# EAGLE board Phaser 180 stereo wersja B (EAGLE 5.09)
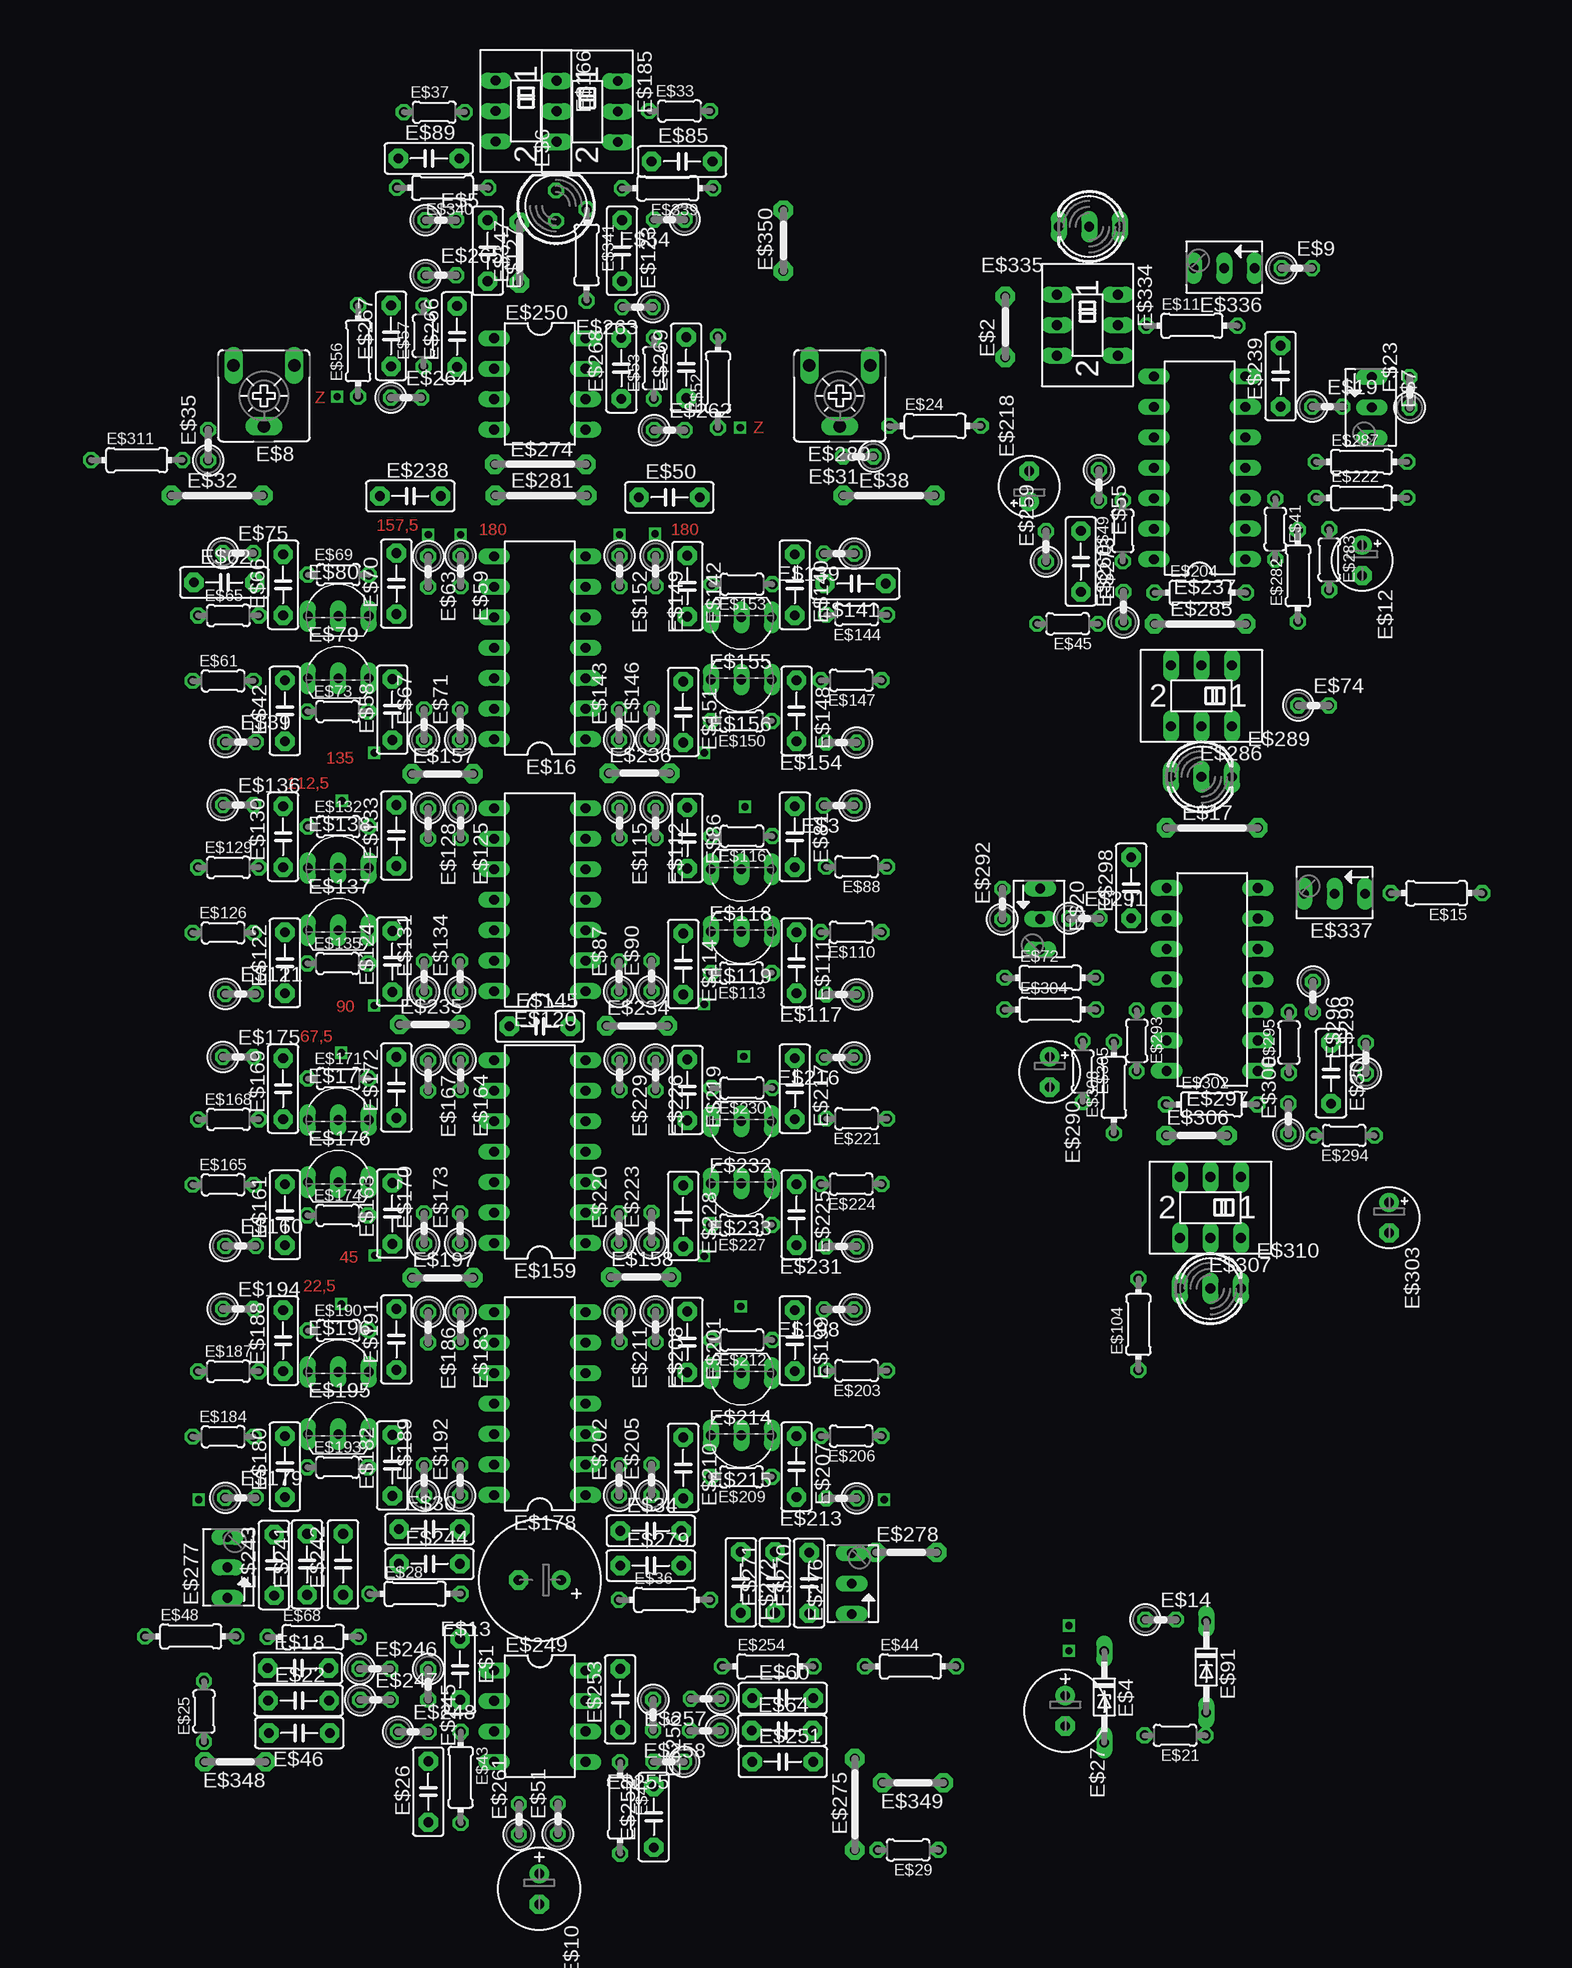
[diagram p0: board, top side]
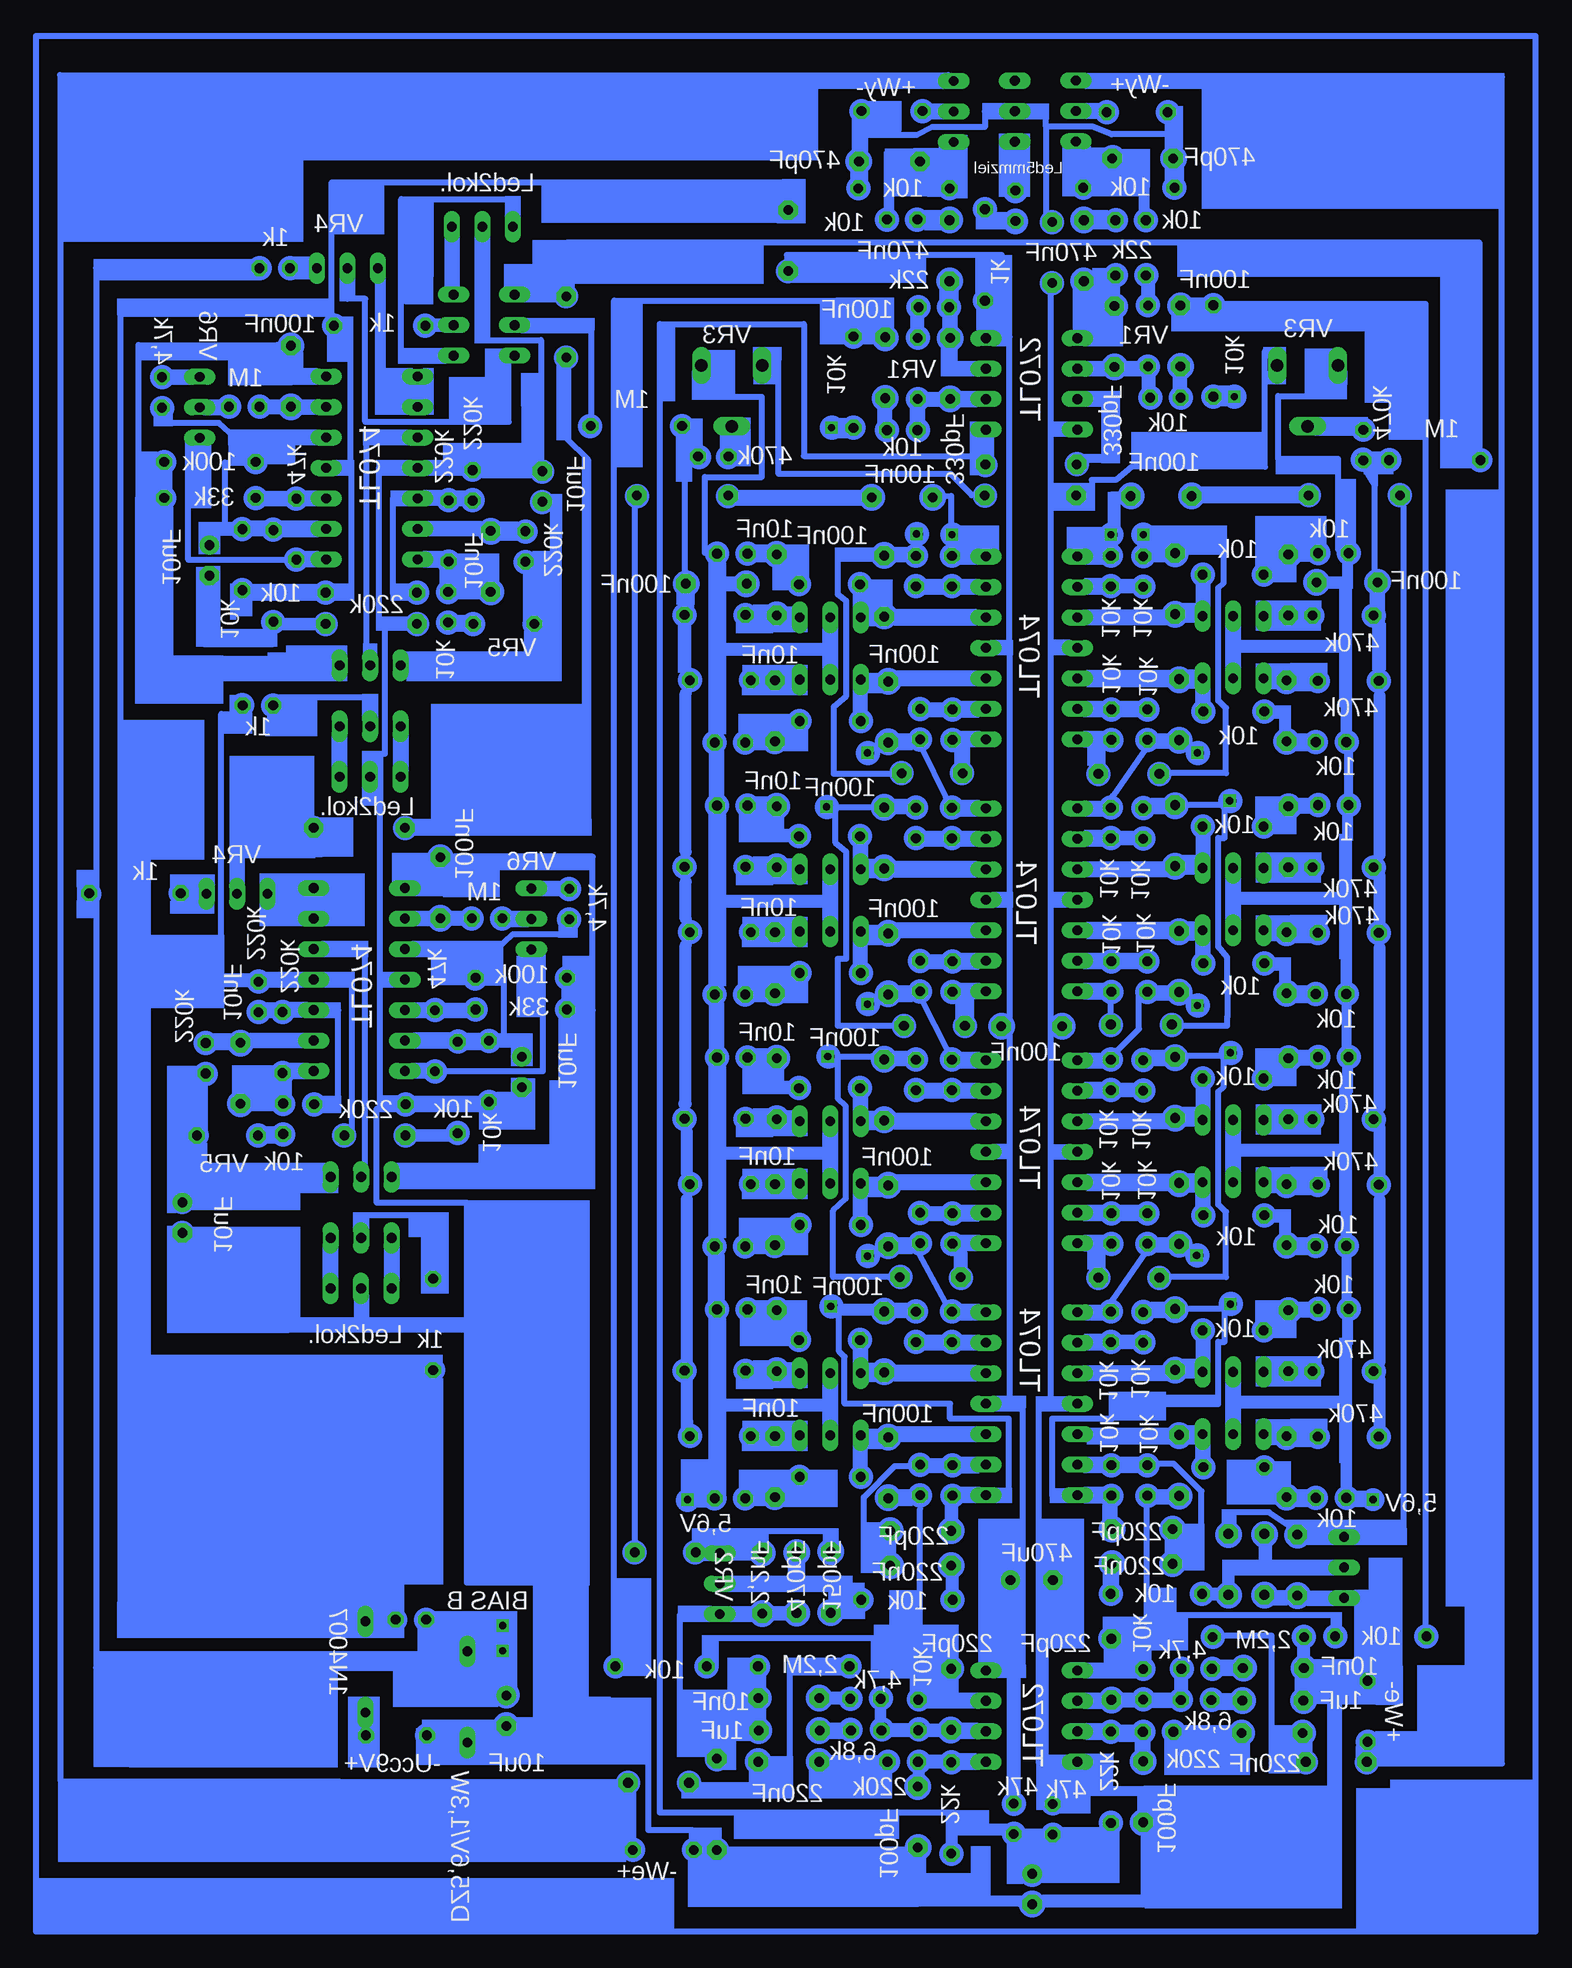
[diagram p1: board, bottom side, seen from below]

No outline drawn. Coordinates in mm, seen from the top.
Copper layers (1*16): Top 0.035mm / dielectric 1.5mm / Bottom 0.035mm
Design rules "default": minimum track width 10mil, minimum drill 24mil, track to track 8mil, track to pad 8mil, pad to pad 8mil, via to via 8mil, smd to smd 8mil, copper to edge 40mil, drill to drill 8mil, minimum pad ring 10mil, minimum via ring 8mil, stop-mask expansion 4mil, vias tented up to drill 0mil, thermal gap 10mil

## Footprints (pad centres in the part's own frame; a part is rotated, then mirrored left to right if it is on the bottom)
C5B2.5 = drill 0.813 pad 1.6 octagon: 1 -2.54,0; 2 2.54,0
05 = drill 0.813 pad 1.6 octagon: 1 -2.54,0; 2 2.54,0
0207/2V = drill 0.813 octagon: 1 -1.27,0; 2 1.27,0
DO34Z7 = drill 0.813 long: A 3.81,0; C -3.81,0
LED5MM = drill 0.813 octagon: A -1.27,0; K 1.27,0
B64Y = drill 0.813 long: A 2.54,0; E -2.54,0; S 0,0
CA6V = drill 1.016 long: A -2.54,-2.54; E 2.54,-2.54; S 0,2.54
E2,5-7 = drill 0.813 pad 1.6 round: + -1.27,0 | drill 0.813 pad 1.6 octagon: - 1.27,0
0204/7 = drill 0.813 octagon: 1 -3.81,0; 2 3.81,0
E2,5-5 = drill 0.813 pad 1.6 round: + -1.27,0 | drill 0.813 pad 1.6 octagon: - 1.27,0
E3,5-10 = drill 0.813 pad 1.6 round: + -1.778,0 | drill 0.813 pad 1.6 octagon: - 1.778,0
DIL14 = drill 0.813 long: 1 -7.62,-3.81; 2 -5.08,-3.81; 3 -2.54,-3.81; 4 0,-3.81; 5 2.54,-3.81; 6 5.08,-3.81; 7 7.62,-3.81; 8 7.62,3.81; 9 5.08,3.81; 10 2.54,3.81; 11 0,3.81; 12 -2.54,3.81; 13 -5.08,3.81; 14 -7.62,3.81
07 = drill 0.813 pad 1.6 octagon: 1 -3.81,0; 2 3.81,0
0204/5 = drill 0.813 octagon: 1 -2.54,0; 2 2.54,0
TO92- = drill 0.813 long: 1 2.54,0; 2 0,0; 3 -2.54,0
DO34-7 = drill 0.813 long: A 3.81,0; C -3.81,0
A68-A31 = drill 0.813 long: 1 -2.54,-2.54; 2 0,-2.54; 3 2.54,-2.54; 4 -2.54,2.54; 5 0,2.54; 6 2.54,2.54
DIL08 = drill 0.813 long: 1 -3.81,-3.81; 2 -1.27,-3.81; 3 1.27,-3.81; 4 3.81,-3.81; 5 3.81,3.81; 6 1.27,3.81; 7 -1.27,3.81; 8 -3.81,3.81
DUOLED-A-5MM = drill 0.813 long: A 0,0; CR 2.54,0; CX -2.54,0

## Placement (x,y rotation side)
E$1  [C5B2.5]  35.65,22.15 270 top
E$2  [05]  81.1,134.05 90 top
E$3  [0207/2V]  67.25,94.15 180 top
E$4  [DO34Z7]  89.35,19.85 270 top
E$5  [0207/2V]  34.05,142.95 0 top
E$6  [LED5MM]  43.65,144.15 90 top
E$7  [B64Y]  111.65,127.35 270 top
E$8  [CA6V]  19.3,128.3 180 top
E$9  [0207/2V]  105.4,138.95 0 top
E$10  [E2,5-7]  42.25,3.85 270 top
E$11  [0204/7]  96.65,134.15 0 top
E$12  [E2,5-5]  110.85,114.6 270 top
E$13  [E3,5-10]  42.3,29.6 180 top
E$14  [0207/2V]  94.05,26.3 0 top
E$15  [0204/7]  117.05,86.85 180 top
E$16  [DIL14]  42.3,107.3 90 top
E$17  [07]  98.35,92.3 0 top
E$18  [C5B2.5]  22.15,22.25 0 top
E$19  [0207/2V]  107.95,127.4 0 top
E$20  [B64Y]  84,84.7 270 top
E$21  [0204/5]  95.25,16.65 180 top
E$22  [C5B2.5]  22.2,19.55 0 top
E$23  [0207/2V]  114.8,128.6 90 top
E$24  [0204/7]  75.25,125.8 0 top
E$25  [0204/5]  14.3,18.65 90 top
E$26  [C5B2.5]  33,11.95 90 top
E$27  [E2,5-7]  86.1,18.7 270 top
E$28  [0204/7]  31.9,28.45 0 top
E$29  [0204/5]  73,7.1 180 top
E$30  [C5B2.5]  33.1,33.85 0 top
E$31  [0207/2V]  68.85,123.25 180 top
E$32  [07]  15.4,120 0 top
E$33  [0204/5]  53.95,152.05 0 top
E$34  [C5B2.5]  51.55,33.7 0 top
E$35  [0207/2V]  14.65,124.2 90 top
E$36  [0204/7]  52.7,27.95 0 top
E$37  [0204/5]  33.5,151.95 0 top
E$38  [07]  71.4,120 0 top
E$39  [0207/2V]  17.35,99.45 0 top
E$41  [0204/5]  103.6,117.2 270 top
E$42  [C5B2.5]  21.05,102.05 90 top
E$43  [0204/7]  35.7,13.15 270 top
E$44  [0204/7]  73.2,22.4 0 top
E$45  [0204/5]  86.3,109.3 180 top
E$46  [C5B2.5]  22.25,16.85 180 top
E$47  [0204/7]  49,10.6 270 top
E$48  [0204/7]  13.2,24.9 0 top
E$49  [0204/5]  90.9,117.05 90 top
E$50  [C5B2.5]  53.1,119.85 0 top
E$51  [0207/2V]  43.8,9.7 90 top
E$52  [0204/7]  57.15,129.45 90 top
E$53  [0204/5]  51.8,130.6 90 top
E$54  [0207/2V]  53.1,143 180 top
E$55  [0207/2V]  88.9,120.85 270 top
E$56  [0204/7]  27.15,132.05 90 top
E$57  [0204/5]  32.6,133.3 90 top
E$58  [C5B2.5]  30,102.15 90 top
E$59  [0207/2V]  35.7,113.7 270 top
E$60  [C5B2.5]  62.55,19.75 0 top
E$61  [0204/5]  15.9,104.55 0 top
E$62  [C5B2.5]  16,112.75 0 top
E$63  [0207/2V]  33,113.65 270 top
E$64  [C5B2.5]  62.5,17.05 0 top
E$65  [0204/5]  16.35,110 0 top
E$66  [C5B2.5]  20.9,112.55 90 top
E$67  [0207/2V]  32.65,100.9 90 top
E$68  [0204/7]  23.4,24.85 0 top
E$69  [0204/5]  25.5,113.4 0 top
E$70  [C5B2.5]  30.35,112.65 90 top
E$71  [0207/2V]  35.65,100.9 90 top
E$72  [0204/7]  84.85,79.8 0 top
E$73  [0204/5]  25.45,102 0 top
E$74  [0207/2V]  106.8,102.5 0 top
E$75  [0207/2V]  17.15,115.2 0 top
E$79  [TO92-]  25.5,104.75 0 top
E$80  [TO92-]  25.5,109.95 0 top
E$81  [C5B2.5]  63.55,91.55 270 top
E$85  [C5B2.5]  54.15,147.85 0 top
E$86  [C5B2.5]  54.6,91.45 270 top
E$87  [0207/2V]  48.9,79.9 90 top
E$88  [0204/5]  68.7,89.05 180 top
E$89  [C5B2.5]  33.05,148.1 0 top
E$90  [0207/2V]  51.6,79.95 90 top
E$91  [DO34-7]  97.85,22.35 270 top
E$104  [0204/7]  92.2,50.9 90 top
E$110  [0204/5]  68.25,83.6 180 top
E$111  [C5B2.5]  63.7,81.05 270 top
E$112  [0207/2V]  51.95,92.7 270 top
E$113  [0204/5]  59.1,80.2 180 top
E$114  [C5B2.5]  54.25,80.95 270 top
E$115  [0207/2V]  48.95,92.7 270 top
E$116  [0204/5]  59.15,91.6 180 top
E$117  [0207/2V]  67.45,78.4 180 top
E$118  [TO92-]  59.1,88.85 180 top
E$119  [TO92-]  59.1,83.65 180 top
E$120  [DIL14]  42.3,86.3 90 top
E$121  [0207/2V]  17.35,78.45 0 top
E$122  [C5B2.5]  21.05,81.05 90 top
E$123  [C5B2.5]  49.15,140.4 270 top
E$124  [C5B2.5]  30,81.15 90 top
E$125  [0207/2V]  35.7,92.7 270 top
E$126  [0204/5]  15.9,83.55 0 top
E$127  [C5B2.5]  37.95,140.4 270 top
E$128  [0207/2V]  33,92.65 270 top
E$129  [0204/5]  16.35,89 0 top
E$130  [C5B2.5]  20.9,91.55 90 top
E$131  [0207/2V]  32.65,79.9 90 top
E$132  [0204/5]  25.5,92.4 0 top
E$133  [C5B2.5]  30.35,91.65 90 top
E$134  [0207/2V]  35.65,79.9 90 top
E$135  [0204/5]  25.45,81 0 top
E$136  [0207/2V]  17.15,94.2 0 top
E$137  [TO92-]  25.5,83.75 0 top
E$138  [TO92-]  25.5,88.95 0 top
E$139  [0207/2V]  67.25,115.15 180 top
E$140  [C5B2.5]  63.55,112.55 270 top
E$141  [C5B2.5]  68.6,112.65 180 top
E$142  [C5B2.5]  54.6,112.45 270 top
E$143  [0207/2V]  48.9,100.9 90 top
E$144  [0204/5]  68.7,110.05 180 top
E$145  [C5B2.5]  42.3,75.75 0 top
E$146  [0207/2V]  51.6,100.95 90 top
E$147  [0204/5]  68.25,104.6 180 top
E$148  [C5B2.5]  63.7,102.05 270 top
E$149  [0207/2V]  51.95,113.7 270 top
E$150  [0204/5]  59.1,101.2 180 top
E$151  [C5B2.5]  54.25,101.95 270 top
E$152  [0207/2V]  48.95,113.7 270 top
E$153  [0204/5]  59.15,112.6 180 top
E$154  [0207/2V]  67.45,99.4 180 top
E$155  [TO92-]  59.1,109.85 180 top
E$156  [TO92-]  59.1,104.65 180 top
E$157  [05]  34.2,96.8 0 top
E$158  [05]  50.75,54.85 0 top
E$159  [DIL14]  42.3,65.3 90 top
E$160  [0207/2V]  17.35,57.45 0 top
E$161  [C5B2.5]  21.05,60.05 90 top
E$163  [C5B2.5]  30,60.15 90 top
E$164  [0207/2V]  35.7,71.7 270 top
E$165  [0204/5]  15.9,62.55 0 top
E$166  [A68-A31]  41.15,152.05 270 top
E$167  [0207/2V]  33,71.65 270 top
E$168  [0204/5]  16.35,68 0 top
E$169  [C5B2.5]  20.9,70.55 90 top
E$170  [0207/2V]  32.65,58.9 90 top
E$171  [0204/5]  25.5,71.4 0 top
E$172  [C5B2.5]  30.35,70.65 90 top
E$173  [0207/2V]  35.65,58.9 90 top
E$174  [0204/5]  25.45,60 0 top
E$175  [0207/2V]  17.15,73.2 0 top
E$176  [TO92-]  25.5,62.75 0 top
E$177  [TO92-]  25.5,67.95 0 top
E$178  [DIL14]  42.3,44.3 90 top
E$179  [0207/2V]  17.35,36.45 0 top
E$180  [C5B2.5]  21.05,39.05 90 top
E$182  [C5B2.5]  30,39.15 90 top
E$183  [0207/2V]  35.7,50.7 270 top
E$184  [0204/5]  15.9,41.55 0 top
E$185  [A68-A31]  46.25,152 270 top
E$186  [0207/2V]  33,50.65 270 top
E$187  [0204/5]  16.35,47 0 top
E$188  [C5B2.5]  20.9,49.55 90 top
E$189  [0207/2V]  32.65,37.9 90 top
E$190  [0204/5]  25.5,50.4 0 top
E$191  [C5B2.5]  30.35,49.65 90 top
E$192  [0207/2V]  35.65,37.9 90 top
E$193  [0204/5]  25.45,39 0 top
E$194  [0207/2V]  17.15,52.2 0 top
E$195  [TO92-]  25.5,41.75 0 top
E$196  [TO92-]  25.5,46.95 0 top
E$197  [05]  34.2,54.8 0 top
E$198  [0207/2V]  67.25,52.15 180 top
E$199  [C5B2.5]  63.55,49.55 270 top
E$201  [C5B2.5]  54.6,49.45 270 top
E$202  [0207/2V]  48.9,37.9 90 top
E$203  [0204/5]  68.7,47.05 180 top
E$204  [0204/7]  97.35,111.9 0 top
E$205  [0207/2V]  51.6,37.95 90 top
E$206  [0204/5]  68.25,41.6 180 top
E$207  [C5B2.5]  63.7,39.05 270 top
E$208  [0207/2V]  51.95,50.7 270 top
E$209  [0204/5]  59.1,38.2 180 top
E$210  [C5B2.5]  54.25,38.95 270 top
E$211  [0207/2V]  48.95,50.7 270 top
E$212  [0204/5]  59.15,49.6 180 top
E$213  [0207/2V]  67.45,36.4 180 top
E$214  [TO92-]  59.1,46.85 180 top
E$215  [TO92-]  59.1,41.65 180 top
E$216  [0207/2V]  67.25,73.15 180 top
E$217  [C5B2.5]  63.55,70.55 270 top
E$218  [E2,5-5]  83.1,120.75 90 top
E$219  [C5B2.5]  54.6,70.45 270 top
E$220  [0207/2V]  48.9,58.9 90 top
E$221  [0204/5]  68.7,68.05 180 top
E$222  [0204/7]  110.8,119.8 0 top
E$223  [0207/2V]  51.6,58.95 90 top
E$224  [0204/5]  68.25,62.6 180 top
E$225  [C5B2.5]  63.7,60.05 270 top
E$226  [0207/2V]  51.95,71.7 270 top
E$227  [0204/5]  59.1,59.2 180 top
E$228  [C5B2.5]  54.25,59.95 270 top
E$229  [0207/2V]  48.95,71.7 270 top
E$230  [0204/5]  59.15,70.6 180 top
E$231  [0207/2V]  67.45,57.4 180 top
E$232  [TO92-]  59.1,67.85 180 top
E$233  [TO92-]  59.1,62.65 180 top
E$234  [05]  50.4,75.8 0 top
E$235  [05]  33.15,75.9 0 top
E$236  [05]  50.6,96.85 0 top
E$237  [DIL14]  97.3,122.3 90 top
E$238  [C5B2.5]  31.5,119.95 0 top
E$239  [C5B2.5]  104.05,129.95 90 top
E$241  [C5B2.5]  22.9,30.9 90 top
E$242  [C5B2.5]  25.9,30.9 90 top
E$243  [C5B2.5]  20.15,30.85 90 top
E$244  [C5B2.5]  33.1,30.95 0 top
E$245  [0207/2V]  33,20.9 270 top
E$246  [0207/2V]  28.55,22.2 0 top
E$247  [0207/2V]  28.6,19.6 0 top
E$248  [0207/2V]  31.75,16.95 0 top
E$249  [DIL08]  42.3,18.25 270 top
E$250  [DIL08]  42.3,129.3 270 top
E$251  [C5B2.5]  62.55,14.45 0 top
E$252  [C5B2.5]  51.8,9.85 90 top
E$253  [C5B2.5]  49,19.65 90 top
E$254  [0204/7]  61.3,22.4 0 top
E$255  [0207/2V]  53.05,14.45 180 top
E$256  [0207/2V]  51.75,18.35 270 top
E$257  [0207/2V]  56.15,19.7 180 top
E$258  [0207/2V]  56.1,17.05 180 top
E$259  [0207/2V]  84.5,115.75 90 top
E$260  [0207/2V]  90.95,110.7 90 top
E$261  [0207/2V]  40.55,9.65 90 top
E$262  [0207/2V]  53.1,125.45 0 top
E$263  [0207/2V]  50.45,135.7 180 top
E$264  [0207/2V]  31.15,128.15 0 top
E$265  [0207/2V]  34.05,138.35 0 top
E$266  [C5B2.5]  35.4,133.25 90 top
E$267  [C5B2.5]  29.9,133.3 90 top
E$268  [C5B2.5]  49.1,130.6 90 top
E$269  [C5B2.5]  54.5,130.65 90 top
E$270  [C5B2.5]  64.75,29.35 90 top
E$271  [C5B2.5]  61.9,29.4 90 top
E$272  [C5B2.5]  59.05,29.4 270 top
E$273  [C5B2.5]  87.4,114.5 270 top
E$274  [07]  42.35,122.6 0 top
E$275  [07]  68.55,10.9 90 top
E$276  [B64Y]  68.3,29.3 90 top
E$277  [B64Y]  16.25,30.65 90 top
E$278  [05]  72.85,31.9 0 top
E$279  [C5B2.5]  51.55,30.8 0 top
E$280  [CA6V]  67.3,128.3 180 top
E$281  [07]  42.4,120 0 top
E$282  [0204/7]  105.5,113.3 90 top
E$283  [0204/5]  108.1,114.65 270 top
E$285  [07]  97.35,109.3 0 top
E$286  [A68-A31]  97.45,103.3 180 top
E$287  [0204/7]  110.8,122.8 0 top
E$289  [DUOLED-A-5MM]  97.45,96.55 0 top
E$290  [E2,5-5]  84.8,71.95 270 top
E$291  [0207/2V]  87.7,84.75 0 top
E$292  [0207/2V]  80.85,85.95 90 top
E$293  [0204/5]  92.05,74.55 270 top
E$294  [0204/5]  109.35,66.65 180 top
E$295  [0204/5]  104.75,74.4 90 top
E$296  [0207/2V]  106.75,78.2 270 top
E$297  [DIL14]  98.35,79.65 90 top
E$298  [C5B2.5]  91.6,87.3 90 top
E$299  [0207/2V]  111.15,73.1 90 top
E$300  [0207/2V]  104.7,68.05 90 top
E$301  [C5B2.5]  108.25,71.85 270 top
E$302  [0204/7]  98.3,69.25 0 top
E$303  [E2,5-5]  113.1,59.8 270 top
E$304  [0204/7]  84.85,77.15 0 top
E$305  [0204/5]  87.55,72 270 top
E$306  [05]  97.05,66.65 0 top
E$307  [A68-A31]  98.2,60.65 180 top
E$308  [0204/7]  90.15,70.65 90 top
E$310  [DUOLED-A-5MM]  98.2,53.9 0 top
E$311  [0204/7]  8.7,122.95 0 top
E$334  [A68-A31]  87.95,134.2 270 top
E$335  [DUOLED-A-5MM]  88.1,142.4 180 top
E$336  [B64Y]  99.35,138.95 180 top
E$337  [B64Y]  108.55,86.8 180 top
E$339  [0204/7]  52.95,145.6 180 top
E$340  [0204/7]  34.2,145.65 180 top
E$341  [0204/7]  46.2,140.05 270 top
E$347  [05]  40.6,140.25 90 top
E$348  [05]  16.9,14.45 180 top
E$349  [05]  73.4,12.7 180 top
E$350  [05]  62.6,141.25 90 top

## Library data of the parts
E$1 E$18 E$22 E$26 E$30 E$34 E$42 E$46 E$50 E$58 E$60 E$62 E$64 E$66 E$70 E$81 E$85 E$86 E$89 E$111 E$114 E$122-E$124 E$127 E$130 E$133 E$140-E$142 E$145 E$148 E$151 E$161 E$163 E$169 E$172 E$180 E$182 E$188 E$191 E$199 E$201 E$207 E$210 E$217 E$219 E$225 E$228 E$238 E$239 E$241-E$244 E$251-E$253 E$266-E$273 E$279 E$298 E$301 = capacitor-wima
E$2 E$17 E$32 E$38 E$157 E$158 E$197 E$234-E$236 E$274 E$275 E$278 E$281 E$285 E$306 E$347-E$350 = jumper
E$3 E$5 E$9-E$15 E$19 E$21 E$23-E$25 E$27-E$29 E$31 E$33 E$35-E$37 E$39 E$41 E$43-E$45 E$47-E$49 E$51-E$57 E$59 E$61 E$63 E$65 E$67-E$69 E$71-E$75 E$87 E$88 E$90 E$104 E$110 E$112 E$113 E$115-E$117 E$121 E$125 E$126 E$128 E$129 E$131 E$132 E$134-E$136 E$139 E$143 E$144 E$146 E$147 E$149 E$150 E$152-E$154 E$160 E$164 E$165 E$167 E$168 E$170 E$171 E$173-E$175 E$179 E$183 E$184 E$186 E$187 E$189 E$190 E$192-E$194 E$198 E$202-E$206 E$208 E$209 E$211-E$213 E$216 E$218 E$220-E$224 E$226 E$227 E$229-E$231 E$245-E$248 E$254-E$265 E$282 E$283 E$287 E$290-E$296 E$299 E$300 E$302-E$305 E$308 E$311 E$339-E$341 = rcl
E$4 E$91 = diode
E$6 E$289 E$310 E$335 = led
E$7 E$8 E$20 E$276 E$277 E$280 E$336 E$337 = pot
E$16 E$120 E$159 E$178 E$237 E$249 E$250 E$297 = analog-devices
E$79 E$80 E$118 E$119 E$137 E$138 E$155 E$156 E$176 E$177 E$195 E$196 E$214 E$215 E$232 E$233 = transistor-fet
E$166 E$185 E$286 E$307 E$334 = switch

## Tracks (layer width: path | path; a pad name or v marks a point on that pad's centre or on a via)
S$1
  Bottom 0.5: 81,137.65 81,141.1 5,141.1 5,123.85
S$2
  Bottom 0.5: 96.5,79.85 96.6,79.85 96.6,94.65 97.4,94.65 97.4,95.75
S$3
  Bottom 0.5: 37.05,145.65 32.8,145.65 32.8,143.8
S$4
  Bottom 0.5: 107.7,79.6 109.85,79.6 109.85,101.8 108.1,101.8 108.1,101.85
S$5
  Bottom 0.5: 108.55,87.65 108.55,92.3 103,92.3
S$6
  Bottom 0.5: 97.5,103.05 97.5,103.15 105.65,103.15
S$7
  Bottom 0.5: 51.45,145.9 54.35,145.9 54.35,143.9
S$8
  Bottom 0.5: 81.1,130.6 81.1,124.8 79.3,123 79.3,92.35 93.65,92.35
S$9
  Bottom 0.5: 98.2,53 98.2,50.6 89.5,50.6
S$12
  Bottom 0.5: 87.75,79.8 86.3,79.8 86.3,75.1
S$41
  Bottom 0.406: 17.65,112.8 15.8,112.8 15.8,114.5
S$42
  Bottom 0.406: 68.8,80.8 68.8,79.1
S$43
  Bottom 0.406: 15.8,93.5 15.8,91.8
S$44
  Bottom 0.406: 68.8,101.8 68.8,100.1
S$45
  Bottom 0.5: 32.8,98.9 35.55,94.95
S$46
  Bottom 0.5: 29.15,94.2 26.2,94.2 26.2,91.45 26.75,91.45 26.75,82.4 26,81.5 26,78.55
S$47
  Bottom 0.5: 26,78.6 26,76.5
S$48
  Bottom 0.5: 30.8,96.85 26.1,96.85 26.1,102.3 26.75,102.9 26.75,112.3 26.3,112.7 26.3,115.3 29.5,115.3
S$49
  Bottom 0.5: 45.1,36.65 44.2,36.65 44.2,43.05 49.1,43.05 49.1,44.3 57.9,44.3 57.9,48.2 58.35,48.65 58.35,52.2 55.75,52.2
S$50
  Bottom 0.5: 49.5,52.75 51.65,56.75
S$51
  Bottom 0.5: 54.2,54.85 58.85,54.85 58.85,60.4 57.8,61.4 57.8,69.1 58.45,69.75 58.45,73.25 55.65,73.25
S$52
  Bottom 0.5: 49.35,73.85 51.4,77.85
S$53
  Bottom 0.406: 15.8,70.8 15.8,72.5
S$54
  Bottom 0.406: 15.8,49.8 15.8,51.5
S$55
  Bottom 0.5: 35.55,52.95 32.8,56.9
S$56
  Bottom 0.5: 29.15,52.2 26.2,52.2 26.2,49.45 26.75,49.45
S$57
  Bottom 0.5: 39.55,36.65 40.6,36.65 40.6,43.05 35.6,43.05 35.6,44.25 26.75,44.25 26.75,49.35
S$58
  Bottom 0.5: 30.8,54.85 26.1,54.85 26.1,60.3 26.75,60.9 26.75,70.3 26.3,70.7 26.3,73.3 29.5,73.3
S$59
  Bottom 1: 71.15,90.3 71.15,103.5
S$60
  Bottom 0.406: 68.8,58.1 68.8,59.8
S$61
  Bottom 0.5: 53.95,75.8 58.45,75.8 58.45,81.4 57.75,81.4 57.75,90.3 58.65,91.05 58.65,94.05 55.6,94.05
S$62
  Bottom 0.5: 49.45,94.85 51.4,98.85
S$63
  Bottom 0.5: 54.15,96.8 58.8,96.8 58.8,102.4 57.75,103.3 57.75,111.2 58.45,111.75 58.45,115.2 55.6,115.2
S$64  (via drill 0.6)
  other vias: 48.95,116.75
S$65
  Bottom 0.5: 35.7,76.5 35.7,77.65
S$66  (via drill 0.6)
  other vias: 56,98.55
S$67
  Bottom 0.5: 35.25,73.7 35.2,73.7 33.35,75.55 33.35,78.25 33.3,78.3
S$68
  Bottom 0.5: 29.65,75.8 26,75.8 26,76.55
S$69  (via drill 0.6)
  other vias: 56,77.6
S$70  (via drill 0.6)
  other vias: 56,56.6
S$71  (via drill 0.6)
  other vias: 33,116.75
S$72  (via drill 0.6)
  other vias: 25.8,94.55
S$73  (via drill 0.6)
  other vias: 25.75,73.55
S$74  (via drill 0.6)
  other vias: 25.75,52.6
S$75  (via drill 0.6)
  other vias: 51.9,116.8
S$76  (via drill 0.6)
  other vias: 59.4,94.05
S$77  (via drill 0.6)
  other vias: 59.3,73.25
S$78  (via drill 0.6)
  other vias: 59.05,52.4
S$79  (via drill 0.6)
  other vias: 35.7,116.75
S$80  (via drill 0.6)
  other vias: 28.5,98.55
S$81  (via drill 0.6)
  other vias: 28.5,77.5
S$82  (via drill 0.6)
  other vias: 28.55,56.65
S$83
  Bottom 0.5: 39.6,44.2 40.7,44.2 40.7,107.4 39.5,107.4
S$84
  Bottom 0.5: 44.85,44.35 44.1,44.35 44.1,107.3 44.15,107.3 | 44.15,107.3 45.2,107.3 | 44.15,107.3 44.15,133.2 45.2,133.2
S$85
  Bottom 0.5: 26.4,24.95 22.3,24.95 22.3,16.85 20.6,16.85
S$86
  Bottom 0.5: 29.5,33.85 28.15,33.85 28.15,37 30.45,39.3 31.75,39.3
S$87
  Bottom 0.5: 55.15,33.65 56.3,33.65 56.3,36.5 53.7,39.1 52.6,39.1
S$88
  Bottom 0.5: 58.55,22.4 62.45,22.4 62.45,14.35 64.2,14.35
S$89
  Bottom 0.5: 34.5,24.75 32.7,24.75 32.7,35.7
S$90
  Bottom 0.5: 50.15,22.35 51.6,22.35 51.6,35.55
S$91
  Bottom 0.5: 39.45,14.4 41.7,14.4 41.7,44.3 40.2,44.3 40.2,44.25
S$92
  Bottom 0.5: 45.2,22.15 43.05,22.15 43.05,44.3 44.25,44.3
S$93
  Bottom 0.5: 39.6,8.35 35.7,8.35 35.7,8.55
S$94
  Bottom 0.5: 44.7,8.55 49,8.55 49,7.7
S$95
  Bottom 0.5: 40.8,11.9 40.8,14.2
S$96
  Bottom 0.5: 44,11.9 43.8,12 43.8,21.7
S$97
  Bottom 0.5: 37.55,14.4 35.75,14.4 35.75,12.15 33.05,12.15 33.05,10.3
S$98
  Bottom 0.5: 32.95,8.4 32.95,2.55 41.3,2.55
S$99
  Bottom 0.5: 43.35,2.6 51.8,2.6 51.8,6.4
S$100
  Bottom 0.5: 37.45,133.2 35.45,133.2 35.45,134.85
S$101
  Bottom 0.5: 37.55,128.05 35.7,128.05 35.7,123 37.8,123
S$102
  Bottom 0.5: 39.75,107.3 40.7,107.3 40.7,125.5 39.45,125.5 39.45,125.6
S$103
  Bottom 0.5: 49,8.7 49,10.2 73.3,10.2 73.3,134.3 61.3,134.3 61.3,123.3 47.3,123.3
S$104
  Bottom 0.5: 66.05,17.05 68.55,17.05 68.55,15.45
S$105
  Bottom 0.5: 52.65,7.1 67.6,7.1
S$106
  Bottom 0.5: 32.9,12.2 17.4,12.2 17.4,19.5 18.65,19.5
S$107
  Bottom 0.5: 17,26 17,26.65 32.45,26.65
S$108
  Bottom 0.5: 69.45,23.2 69.45,24.75 51.85,24.75
S$109
  Bottom 0.5: 58.3,136.25 77.1,136.25 77.1,23.3
S$110  (via drill 0.6)
  other vias: 59,125.65
S$111  (via drill 0.6)
  other vias: 25.4,128.25
S$112
  Bottom 0.5: 26.1,135.95 9.45,135.95 9.45,25.95
S$113
  Bottom 0.5: 49.7,119.9 49,119.95 49,117.55
S$114
  Bottom 0.5: 56.65,119.9 66.95,119.9
S$115
  Bottom 0.5: 67.4,29.3 61.85,29.3 61.85,31.05
S$116
  Bottom 0.5: 61.9,29.4 59,29.4 59,27.85
S$117
  Bottom 0.5: 64.75,32.9 64.75,33.65 59.05,33.65 59.05,32.85
S$118
  Bottom 0.5: 69.35,26.75 71.6,26.75 71.6,17.05 68.55,17.05
S$119
  Bottom 0.5: 75.35,32.85 75.35,119.1
S$120
  Bottom 0.5: 20.95,34.2 22.5,35.25 25.9,35.25 25.9,34.4
S$121
  Bottom 0.5: 34.95,120.1 35.65,120.1 35.65,117.7
S$122
  Bottom 0.5: 20.1,120.1 28.05,120.1 28.05,120.2
S$123
  Bottom 0.5: 11.3,119.05 11.3,33.3 15.3,33.3
S$124
  Bottom 0.5: 15.3,28.15 15,28.15 15,19.5 17.3,19.5
S$125
  Bottom 0.5: 58.55,136.25 57.15,136.25 57.15,134.05
S$126
  Bottom 0.5: 40.3,119.3 37.3,119.3 37.3,121.3 35.3,121.3 33.95,122.4 22.85,122.4 22.85,132.05
S$127
  Bottom 0.5: 47.3,120 47.3,120.05 49.05,121.8 63.4,121.8 63.4,131.9
S$128
  Bottom 0.5: 70.8,123.2 71.2,121.2 71.2,113.5
S$129
  Bottom 0.5: 69.85,129.85 67.4,129.85 67.4,128.2 64.8,128.2 64.8,121.55 69.55,121.55 69.55,115.2
S$130
  Bottom 1: 71.15,84.7 71.15,87.8
S$131
  Bottom 1: 71.25,69.3 71.15,69.3 71.15,82.5
S$132
  Bottom 1: 71.05,63.5 71.05,66.95
S$133
  Bottom 1: 71.05,47.9 71.05,61.35
S$134
  Bottom 1: 71.05,42.8 71.05,46.15
S$135
  Bottom 1: 13.3,42.3 13.3,46.3
S$136
  Bottom 1: 13.3,47.8 13.3,61.3
S$137
  Bottom 1: 13.3,63.3 13.3,67.3
S$138
  Bottom 1: 13.3,69 13.3,82.3
S$139
  Bottom 1: 13.3,84.3 13.3,88.3
S$140
  Bottom 1: 13.3,90.05 13.3,103.3
S$141
  Bottom 0.5: 16.75,129.85 19.3,129.85 19.3,128.3 21.75,128.3 21.75,123.05 16.75,123.05 16.75,115.5
S$142
  Bottom 0.5: 14.5,122.15 13.7,120.85 13.7,113.55
S$143
  Bottom 0.5: 90,114.65 87.35,114.65 87.35,112.75
S$144
  Bottom 0.5: 94.7,119.75 95.55,119.75 95.55,111.85 94.35,111.85
S$145
  Bottom 0.5: 100.2,111.9 99.05,111.9 99.05,122.35 100.15,122.35
S$146
  Bottom 0.5: 84.45,109.2 84.45,113.5
S$147
  Bottom 0.5: 102.05,129.9 104,129.9 104,131.7
S$148
  Bottom 0.5: 113.95,126.05 110.05,126.05 108.75,124.85 102.15,124.85
S$149
  Bottom 0.5: 109.05,117.25 110.85,117.25 110.85,116.65
S$150
  Bottom 0.5: 104.45,114.65 112.6,114.65 112.6,125.05
S$151
  Bottom 0.5: 110.85,112.55 110.85,112.05
S$152
  Bottom 0.5: 105.2,132.55 116.75,132.55 116.75,119.75 115.5,119.75
S$153
  Bottom 0.5: 97.45,102 97.45,103.2
S$154
  Bottom 0.5: 94.35,124.85 97.8,124.8 97.8,106.55
S$155
  Bottom 0.5: 94.7,106.75 81.7,106.75 81.7,117
S$156
  Bottom 0.5: 99.85,106.4 114.65,106.4 114.65,119.05
S$157
  Bottom 0.5: 94.35,122.3 96.7,122.3 96.7,109.25 94.25,109.25
S$158
  Bottom 0.5: 97.45,97.4 97.45,98.45 96.2,98.45 96.2,109.2
S$159
  Bottom 0.5: 96.8,138.1 96.8,130.35 94.1,130.35
S$160
  Bottom 0.5: 105.65,72 108.3,72 108.3,70.1
S$161
  Bottom 0.5: 100.95,77.1 100.1,77.1 100.1,69.2 101.3,69.2
S$162
  Bottom 0.5: 95.45,69.25 96.6,69.25 96.6,79.7 95.5,79.7
S$163
  Bottom 0.5: 111.2,66.55 111.2,70.85
S$164
  Bottom 0.5: 93.6,87.25 91.65,87.25 91.65,89.05
S$165
  Bottom 0.5: 91.2,72 83.05,72 83.05,82.4
S$166
  Bottom 0.5: 81.7,83.4 85.6,83.4 86.9,82.2 93.5,82.2
S$167
  Bottom 0.5: 86.6,74.6 84.8,74.6 84.8,74
S$168
  Bottom 0.5: 84.8,69.9 84.8,69.4 86.75,69.4
S$169
  Bottom 0.5: 90.45,89.9 78.9,89.9 78.9,77.1 80.15,77.1
S$170
  Bottom 0.5: 101.3,82.2 97.85,82.15 97.85,63.9
S$171
  Bottom 0.5: 100.95,64.1 113.95,64.1
S$172
  Bottom 0.5: 95.8,64.1 81,64.1 81,76.4
S$173
  Bottom 0.5: 101.3,79.65 98.95,79.65 98.95,66.6
S$174
  Bottom 0.5: 98.2,59.35 98.2,60 91.4,60
S$178
  Bottom 0.5: 96.7,68.9 96.9,68.9 96.9,61.05 89.4,61.05 89.4,29.4 81.5,29.4 81.5,17.3 81.35,17.3
S$179
  Bottom 0.5: 106.25,58.5 112.15,58.5
S$207
  Bottom 0.5: 84.55,134.2 79,134.2 79,126.65
S$208
  Bottom 0.5: 99.35,138.05 99.35,136.4 97.85,136.4 97.85,126.15 85.9,126.15 85.9,131.1
S$210
  Bottom 0.5: 99.1,122.65 99.1,134.15 99.7,134.15
S$211
  Bottom 0.5: 88.1,141.35 88.1,132.95 83.2,132.95 83.2,127.55 84.6,127.55 84.6,122.8 84.65,122.8
S$212
  Bottom 0.5: 90.7,137.35 90.7,141.35
S$213
  Bottom 0.5: 85.55,143.3 85.55,144.7 94.85,144.7 94.85,132.05 91.2,132.05
S$241
  Bottom 0.5: 40.7,126.15 40.7,136.95
S$242
  Bottom 0.5: 42.8,152 41.1,152 41.1,150.75 | 41.1,150.75 41.1,143.5 | 41.1,150.75 37.25,150.75 35.65,150.1 30.65,150.1
S$243
  Bottom 0.5: 44.65,152 46.2,152 46.2,150.7 50.6,150.7 51.9,150.05 56.5,150.05
S$244
  Bottom 0.5: 37.6,154.9 3.1,154.9 3.1,14.3 13.3,14.3
S$245
  Bottom 0.5: 49.25,155.05 123.3,155.05 123.28,12.88 76.6,12.8
S$246
  Bottom 0.406: 69.95,12.55 65.2,12.55 65.2,13.55
S$247
  Bottom 0.406: 75.55,8.1 75.55,11.85
S$250
  Bottom 0.5: 44.95,136.3 44.95,140.05
S$251
  Bottom 0.5: 44.8,139.95 44.8,140.05 62.7,140.05 62.7,139.5
S$252
  Bottom 0.5: 62.65,144.8 62.65,146.1 100.65,146.1 100.65,135.15
S$253
  Bottom 0.5: 100.85,135.1 118.3,135.1 118.3,27.3
S$259  (via drill 0.6)
  other vias: 13.85,36.3
S$260  (via drill 0.6)
  other vias: 71,36.3
S$263
  Bottom 0.5: 91.85,16.65 91.85,16.75 85.4,16.75
S$265
  Bottom 0.5: 78.9,16.5 74.25,16.5 74.25,8.75 70.6,8.75 70.6,7.9
S$266
  Bottom 0.5: 107.85,138.95 120.3,138.95 120.3,22.3 87.3,22.3
S$269  (via drill 0.6)
  other vias: 86.4,25.8
S$270  (via drill 0.6)
  other vias: 86.4,23.7
S$271
  Bottom 0.5: 125.3,0.3 125.3,158.3 0.3,158.3 0.3,0.3 125.3,0.3
S$284
  Bottom 0.5: 105.6,108.45 105.6,107.6 111.25,107.6 111.25,112.1
S$285
  Bottom 0.5: 107.95,122.75 109.55,122.75 109.55,117.45
(copper drawn outside any net)
  shapes: Bottom area x1032, Bottom circle x514

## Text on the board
Top: Z | Z | 157,5 | 180 | 180 | 135 | 112,5 | 90 | 67,5 | 45 | 22,5
bNames: -Wy+ | +Wy- | 470pF | Led5mmziel | 470pF | Led2kol. | 10k | 10k | 10k | 10k | VR4 | 1k | 22k | 470nF | 1k | 470nF | 100nF | 22k | 100nF | 100nF | 4,7k | 1k | VR3 | 10k | VR1 | VR3 | VR6 | VR1 | 470k | 330pF | 1M | 10k | 330pF | 1M | TL072 | TL074 | 1M | 10k | 220k | 10k | 470k | 100nF | 100k | 100nF | 220k | 47k | 10uF | 33k | 10nF | 10nF | 10k | 100nF | 10k | 220k | 10k | 100nF | 100nF | 220k | 10uF | 10k | TL074 | 470k | 10k | 10k | 10nF | VR5 | 10k | 10k | 10k | 100nF | 470k | 10k | 1k | 10k | 10nF | 100nF | Led2kol. | 100nF | 10k | 10k | VR4 | 10k | 10k | TL074 | VR6 | 1k | 470k | 4,7k | 470k | 10nF | 1M | 10k | 10k | 100nF | TL074 | 220k | 10k | 100k | 47k | 220k | 10k | 33k | 10nF | 10nF | 100nF | 220k | 100nF | 10k | 10k | 470k | 10uF | 10k | 220k | 10k | 10k | TL074 | 10k | 10nF | 470k | 10k | VR5 | 10k | 100nF | 10k | 10uF | 10k | 10k | 10k | 10nF | 100nF | TL074 | 10k | Led2kol. | 470k | 1k | 10k | 10k | 10nF | 470k | 10k | 10k | 100nF | 5,6V | 10k | 5,6V | 220pF | 470uF | 220pF | 150pF | 470pF | 2,2nF | VR2 | 220nF | 220nF | 10k | BIAS B | 10k | 10k | 2,2M | 4,7k | 220pF | 220pF | 10nF | 10k | 2,2M | 10k | TL072 | 10k | 4,7k | 1uF | 10nF | 1N4007 | 6,8k | 1uF | +We- | 6,8k | 220nF | 220k | 22k | 10uF | DZ5,6V/1,3W | -Ucc9V+ | 100pF | 47k | 47k | 22k | 220k | 220nF | 100pF | -We+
